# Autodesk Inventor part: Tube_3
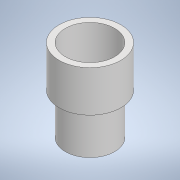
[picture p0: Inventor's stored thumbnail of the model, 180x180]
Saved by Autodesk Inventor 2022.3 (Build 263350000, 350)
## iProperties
Created: 2023-03
Part Number: Tube_3
Material: Generic
Document SubType Name: Modeling
Designer: Manuel Hueso Béjar
Density: 1 g/cm^3
Appearance: Default
Author: Manuel Hueso Béjar
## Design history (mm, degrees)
sketch "Sketch1"
  geometry: C1 r 12 at (0, 0); C2 r 15 at (0, 0); 1 further point
  constraints: 2 centre point, 2 coincident
  dimensions: "d0" = 24 diameter of C1; "d1" = 30 diameter of C2
extrude "Extrusion1" new body sketch "Sketch1" distance "d2" = 20; taper "d3" = 0 deg
extrude "Extrusion2" join sketch "Sketch1" distance "d4" = 20; taper "d5" = 0 deg
body "Solid1"
